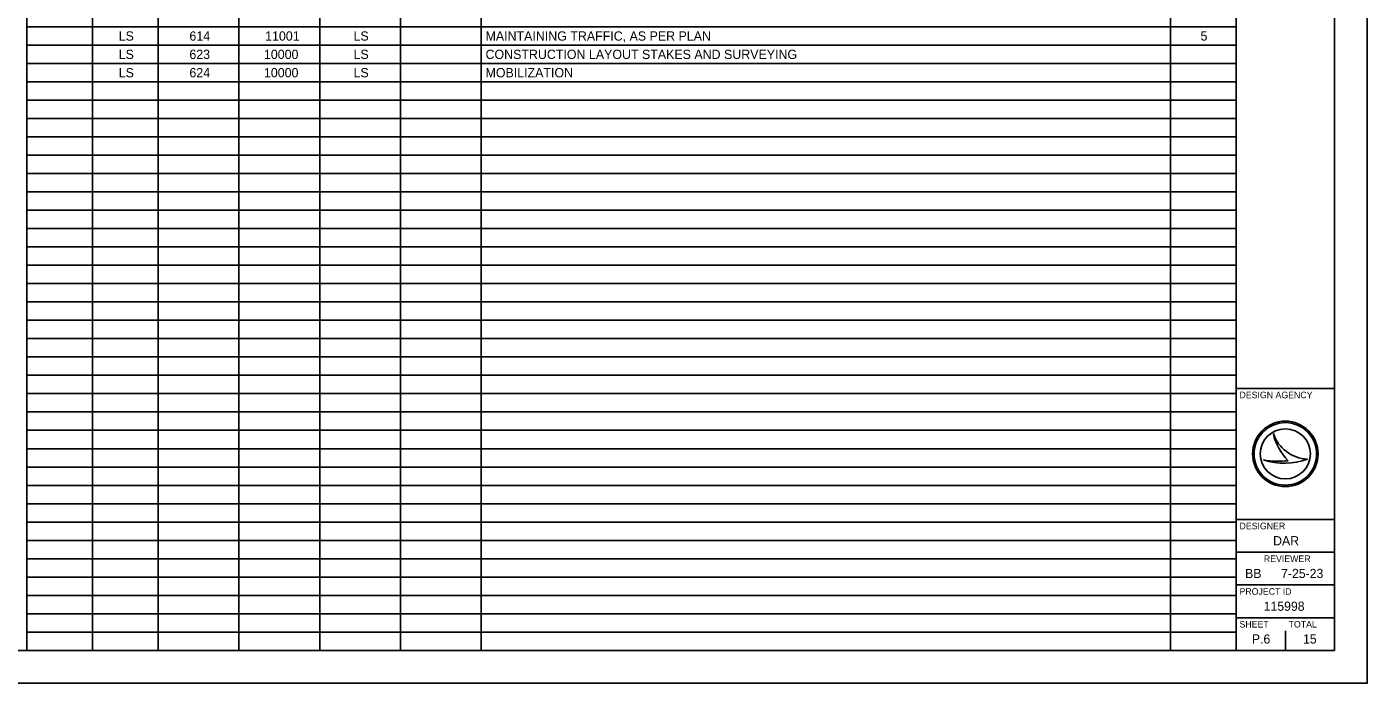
# Model space of a CAD drawing. Extents: x 0 to 34, y 0 to 22.
# Drawn here: x 13.53 to 34, y 0 to 10.02 of the extents above; entities that cross this region are included whole.
import ezdxf

# ---------------------------------------------------------------- set-up
doc = ezdxf.new("R2010")
doc.units = 0
for name, color, linetype in [('Default', 7, 'Continuous'), ('SH_Border', 7, 'Continuous'), ('SH_Cut_Line', 7, 'Continuous'), ('SH_Data', 7, 'Continuous')]:
    doc.layers.add(name, color=color, linetype=linetype)

msp = doc.modelspace()

# ---------------------------------------------------------------- linework, layer by layer
at = {"layer": 'Default'}
for p, q in [((13.531, 10.3), (13.531, 10.02)), ((14.533, 10.3), (14.533, 10.02)), ((15.536, 10.3), (15.536, 10.02)), ((16.77, 10.3), (16.77, 10.02)), ((18.004, 10.3), (18.004, 10.02)), ((19.237, 10.3), (19.237, 10.02)), ((20.471, 10.3), (20.471, 10.02)), ((30.998, 10.3), (30.998, 10.02)), ((32.001, 10.3), (32.001, 10.02)), ((13.531, 10.02), (15.536, 10.02)), ((13.531, 10.02), (13.531, 9.74)), ((14.533, 10.02), (14.533, 9.74)), ((15.536, 10.02), (32.001, 10.02)), ((15.536, 10.02), (15.536, 9.74)), ((16.77, 10.02), (16.77, 9.74)), ((18.004, 10.02), (18.004, 9.74)), ((19.237, 10.02), (19.237, 9.74)), ((20.471, 10.02), (20.471, 9.74)), ((30.998, 10.02), (30.998, 9.74)), ((32.001, 10.02), (32.001, 9.74)), ((13.531, 9.74), (15.536, 9.74)), ((13.531, 9.74), (13.531, 8.9)), ((14.533, 9.74), (14.533, 8.9)), ((15.536, 9.74), (32.001, 9.74)), ((15.536, 9.74), (15.536, 8.9)), ((16.77, 9.74), (16.77, 8.9)), ((18.004, 9.74), (18.004, 8.9)), ((19.237, 9.74), (19.237, 8.9)), ((20.471, 9.74), (20.471, 8.9)), ((30.998, 9.74), (30.998, 8.9)), ((32.001, 9.74), (32.001, 8.9)), ((13.531, 9.46), (15.536, 9.46)), ((15.536, 9.46), (32.001, 9.46)), ((13.531, 9.18), (15.536, 9.18)), ((15.536, 9.18), (32.001, 9.18)), ((13.531, 8.9), (15.536, 8.9)), ((13.531, 8.9), (13.531, 8.34)), ((14.533, 8.9), (14.533, 8.34)), ((15.536, 8.9), (32.001, 8.9)), ((15.536, 8.9), (15.536, 8.34)), ((16.77, 8.9), (16.77, 8.34)), ((18.004, 8.9), (18.004, 8.34)), ((19.237, 8.9), (19.237, 8.34)), ((20.471, 8.9), (20.471, 8.34)), ((30.998, 8.9), (30.998, 8.34)), ((32.001, 8.9), (32.001, 8.34)), ((13.531, 8.62), (15.536, 8.62)), ((15.536, 8.62), (32.001, 8.62)), ((13.531, 8.34), (15.536, 8.34)), ((13.531, 8.34), (13.531, 7.5)), ((14.533, 8.34), (14.533, 7.5)), ((15.536, 8.34), (32.001, 8.34)), ((15.536, 8.34), (15.536, 7.5)), ((16.77, 8.34), (16.77, 7.5)), ((18.004, 8.34), (18.004, 7.5)), ((19.237, 8.34), (19.237, 7.5)), ((20.471, 8.34), (20.471, 7.5)), ((30.998, 8.34), (30.998, 7.5)), ((32.001, 8.34), (32.001, 7.5)), ((13.531, 8.06), (15.536, 8.06)), ((15.536, 8.06), (32.001, 8.06)), ((13.531, 7.78), (15.536, 7.78)), ((15.536, 7.78), (32.001, 7.78)), ((13.531, 7.5), (15.536, 7.5)), ((13.531, 7.5), (13.531, 6.94)), ((14.533, 7.5), (14.533, 6.94)), ((15.536, 7.5), (32.001, 7.5)), ((15.536, 7.5), (15.536, 6.94)), ((16.77, 7.5), (16.77, 6.94)), ((18.004, 7.5), (18.004, 6.94)), ((19.237, 7.5), (19.237, 6.94)), ((20.471, 7.5), (20.471, 6.94)), ((30.998, 7.5), (30.998, 6.94)), ((32.001, 7.5), (32.001, 6.94)), ((13.531, 7.22), (15.536, 7.22)), ((15.536, 7.22), (32.001, 7.22)), ((13.531, 6.94), (15.536, 6.94)), ((13.531, 6.94), (13.531, 6.1)), ((14.533, 6.94), (14.533, 6.1)), ((15.536, 6.94), (32.001, 6.94)), ((15.536, 6.94), (15.536, 6.1)), ((16.77, 6.94), (16.77, 6.1)), ((18.004, 6.94), (18.004, 6.1)), ((19.237, 6.94), (19.237, 6.1)), ((20.471, 6.94), (20.471, 6.1)), ((30.998, 6.94), (30.998, 6.1)), ((32.001, 6.94), (32.001, 6.1)), ((13.531, 6.66), (15.536, 6.66)), ((15.536, 6.66), (32.001, 6.66)), ((13.531, 6.38), (15.536, 6.38)), ((15.536, 6.38), (32.001, 6.38)), ((13.531, 6.1), (15.536, 6.1)), ((13.531, 6.1), (13.531, 4.98)), ((14.533, 6.1), (14.533, 4.98)), ((15.536, 6.1), (32.001, 6.1)), ((15.536, 6.1), (15.536, 4.98)), ((16.77, 6.1), (16.77, 4.98)), ((18.004, 6.1), (18.004, 4.98)), ((19.237, 6.1), (19.237, 4.98)), ((20.471, 6.1), (20.471, 4.98)), ((30.998, 6.1), (30.998, 4.98)), ((32.001, 6.1), (32.001, 4.98)), ((13.531, 5.82), (15.536, 5.82)), ((15.536, 5.82), (32.001, 5.82)), ((13.531, 5.54), (15.536, 5.54)), ((15.536, 5.54), (32.001, 5.54)), ((13.531, 5.26), (15.536, 5.26)), ((15.536, 5.26), (32.001, 5.26)), ((13.531, 4.98), (15.536, 4.98)), ((13.531, 4.98), (13.531, 4.7)), ((14.533, 4.98), (14.533, 4.7)), ((15.536, 4.98), (32.001, 4.98)), ((15.536, 4.98), (15.536, 4.7)), ((16.77, 4.98), (16.77, 4.7)), ((18.004, 4.98), (18.004, 4.7)), ((19.237, 4.98), (19.237, 4.7)), ((20.471, 4.98), (20.471, 4.7)), ((30.998, 4.98), (30.998, 4.7)), ((32.001, 4.98), (32.001, 4.7)), ((13.531, 4.7), (15.536, 4.7)), ((13.531, 4.7), (13.531, 3.58)), ((14.533, 4.7), (14.533, 3.58)), ((15.536, 4.7), (32.001, 4.7)), ((15.536, 4.7), (15.536, 3.58)), ((16.77, 4.7), (16.77, 3.58)), ((18.004, 4.7), (18.004, 3.58)), ((19.237, 4.7), (19.237, 3.58)), ((20.471, 4.7), (20.471, 3.58)), ((30.998, 4.7), (30.998, 3.58)), ((32.001, 4.7), (32.001, 3.58)), ((13.531, 4.42), (15.536, 4.42)), ((15.536, 4.42), (32.001, 4.42)), ((13.531, 4.14), (15.536, 4.14)), ((15.536, 4.14), (32.001, 4.14)), ((13.531, 3.86), (15.536, 3.86)), ((15.536, 3.86), (32.001, 3.86)), ((13.531, 3.58), (15.536, 3.58)), ((13.531, 3.58), (13.531, 3.3)), ((14.533, 3.58), (14.533, 3.3)), ((15.536, 3.58), (32.001, 3.58)), ((15.536, 3.58), (15.536, 3.3)), ((16.77, 3.58), (16.77, 3.3)), ((18.004, 3.58), (18.004, 3.3)), ((19.237, 3.58), (19.237, 3.3)), ((20.471, 3.58), (20.471, 3.3)), ((30.998, 3.58), (30.998, 3.3)), ((32.001, 3.58), (32.001, 3.3)), ((13.531, 3.3), (15.536, 3.3)), ((13.531, 3.3), (13.531, 2.18)), ((14.533, 3.3), (14.533, 2.18)), ((15.536, 3.3), (32.001, 3.3)), ((15.536, 3.3), (15.536, 2.18)), ((16.77, 3.3), (16.77, 2.18)), ((18.004, 3.3), (18.004, 2.18)), ((19.237, 3.3), (19.237, 2.18)), ((20.471, 3.3), (20.471, 2.18)), ((30.998, 3.3), (30.998, 2.18)), ((32.001, 3.3), (32.001, 2.18)), ((13.531, 3.02), (15.536, 3.02)), ((15.536, 3.02), (32.001, 3.02)), ((13.531, 2.74), (15.536, 2.74)), ((15.536, 2.74), (32.001, 2.74)), ((13.531, 2.46), (15.536, 2.46)), ((15.536, 2.46), (32.001, 2.46)), ((13.531, 2.18), (15.536, 2.18)), ((13.531, 2.18), (13.531, 1.9)), ((14.533, 2.18), (14.533, 1.9)), ((15.536, 2.18), (32.001, 2.18)), ((15.536, 2.18), (15.536, 1.9)), ((16.77, 2.18), (16.77, 1.9)), ((18.004, 2.18), (18.004, 1.9)), ((19.237, 2.18), (19.237, 1.9)), ((20.471, 2.18), (20.471, 1.9)), ((30.998, 2.18), (30.998, 1.9)), ((32.001, 2.18), (32.001, 1.9)), ((13.531, 1.9), (15.536, 1.9)), ((13.531, 1.9), (13.531, 0.78)), ((14.533, 1.9), (14.533, 0.78)), ((15.536, 1.9), (32.001, 1.9)), ((15.536, 1.9), (15.536, 0.78)), ((16.77, 1.9), (16.77, 0.78)), ((18.004, 1.9), (18.004, 0.78)), ((19.237, 1.9), (19.237, 0.78)), ((20.471, 1.9), (20.471, 0.78)), ((30.998, 1.9), (30.998, 0.78)), ((32.001, 1.9), (32.001, 0.78)), ((13.531, 1.62), (15.536, 1.62)), ((15.536, 1.62), (32.001, 1.62)), ((13.531, 1.34), (15.536, 1.34)), ((15.536, 1.34), (32.001, 1.34)), ((13.531, 1.06), (15.536, 1.06)), ((15.536, 1.06), (32.001, 1.06)), ((13.531, 0.78), (15.536, 0.78)), ((13.531, 0.78), (13.531, 0.5)), ((14.533, 0.78), (14.533, 0.5)), ((15.536, 0.78), (32.001, 0.78)), ((15.536, 0.78), (15.536, 0.5)), ((16.77, 0.78), (16.77, 0.5)), ((18.004, 0.78), (18.004, 0.5)), ((19.237, 0.78), (19.237, 0.5)), ((20.471, 0.78), (20.471, 0.5)), ((30.998, 0.78), (30.998, 0.5)), ((32.001, 0.78), (32.001, 0.5)), ((13.531, 0.5), (15.536, 0.5)), ((15.536, 0.5), (32.001, 0.5))]:
    msp.add_line(p, q, dxfattribs=at)
at = {"layer": 'SH_Border'}
for p, q in [((32, 0.5), (32, 21.5)), ((32, 4.5), (33.5, 4.5)), ((32, 2.5), (33.5, 2.5)), ((32, 2), (33.5, 2)), ((32, 1.5), (33.5, 1.5)), ((32, 1), (33.5, 1))]:
    msp.add_line(p, q, dxfattribs=at)
msp.add_lwpolyline([(1.5, 21.5), (33.5, 21.5), (33.5, 0.5), (1.5, 0.5)], close=True, dxfattribs=at)
at = {"layer": 'SH_Cut_Line'}
msp.add_lwpolyline([(0, 0), (34, 0), (34, 22), (0, 22)], close=True, dxfattribs=at)
at = {"layer": 'SH_Data'}
for p, q in [((32.567, 3.81), (32.567, 3.81)), ((32.75, 3.5), (32.75, 3.5)), ((32.417, 3.41), (32.417, 3.41)), ((33.087, 3.419), (33.087, 3.419)), ((32.375, 0.675), (32.375, 0.675)), ((32.75, 0.5), (32.75, 0.8))]:
    msp.add_line(p, q, dxfattribs=at)
for radius in [0.5, 0.477, 0.477, 0.382]:
    msp.add_circle((32.75, 3.5), radius, dxfattribs=at)
for centre, radius, start, end in [((33.116, 3.998), 0.58, 198.9257, 198.9319), ((33.347, 3.97), 0.796, 191.6379, 191.6421), ((33.116, 3.998), 0.58, 198.9319, 267.1657), ((33.347, 3.97), 0.796, 191.6421, 226.0947), ((32.739, 4.37), 1.013, 251.4576, 290.0832), ((32.648, 4.654), 1.266, 259.4964, 259.4995), ((32.739, 4.37), 1.013, 251.4527, 251.4576), ((32.648, 4.654), 1.266, 259.4995, 276.6672)]:
    msp.add_arc(centre, radius, start, end, dxfattribs=at)

# ---------------------------------------------------------------- texts
at = {"layer": 'Default'}
for s, height, p in [('LS', 0.1417, (14.934, 9.809)), ('614', 0.1417, (16.014, 9.809)), ('11001', 0.1417, (17.17, 9.809)), ('LS', 0.1417, (18.52, 9.809)), ('MAINTAINING TRAFFIC, AS PER PLAN', 0.14167, (20.536, 9.809)), ('5', 0.142, (31.455, 9.809)), ('LS', 0.1417, (14.934, 9.529)), ('623', 0.1417, (16.013, 9.529)), ('10000', 0.1417, (17.152, 9.529)), ('LS', 0.1417, (18.52, 9.529)), ('CONSTRUCTION LAYOUT STAKES AND SURVEYING', 0.14167, (20.536, 9.529)), ('LS', 0.1417, (14.934, 9.249)), ('624', 0.1417, (16.014, 9.249)), ('10000', 0.1417, (17.152, 9.249)), ('LS', 0.1417, (18.52, 9.249)), ('MOBILIZATION', 0.14167, (20.536, 9.249))]:
    msp.add_text(s, height=height, dxfattribs=at).set_placement(p)
at = {"layer": 'SH_Data'}
for s, height, p in [('DESIGN AGENCY', 0.1, (32.05, 4.35)), ('DESIGNER', 0.1, (32.05, 2.35)), ('DAR', 0.14, (32.564, 2.105)), ('REVIEWER', 0.1, (32.422, 1.85)), ('BB', 0.14, (32.135, 1.605)), ('7-25-23', 0.14, (32.685, 1.605)), ('PROJECT ID', 0.1, (32.05, 1.35)), ('115998', 0.14, (32.419, 1.105)), ('SHEET', 0.1, (32.05, 0.85)), ('TOTAL', 0.1, (32.8, 0.85)), ('P.6', 0.14, (32.239, 0.605)), ('15', 0.14, (33.02, 0.605))]:
    msp.add_text(s, height=height, dxfattribs=at).set_placement(p)

doc.saveas('drawing.dxf')
